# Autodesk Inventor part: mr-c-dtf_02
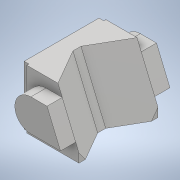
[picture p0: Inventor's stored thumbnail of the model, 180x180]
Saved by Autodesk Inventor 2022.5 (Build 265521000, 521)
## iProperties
Part Number: mr-c-dtf_02
Material: 一般
Document SubType Name: Modeling
Designer: ImaoCorp
Density: 1 g/cm^3
Appearance: 既定
Author: ImaoCorp
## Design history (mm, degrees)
feature "mr-c-dtf_02"
node "ソリッド1"
